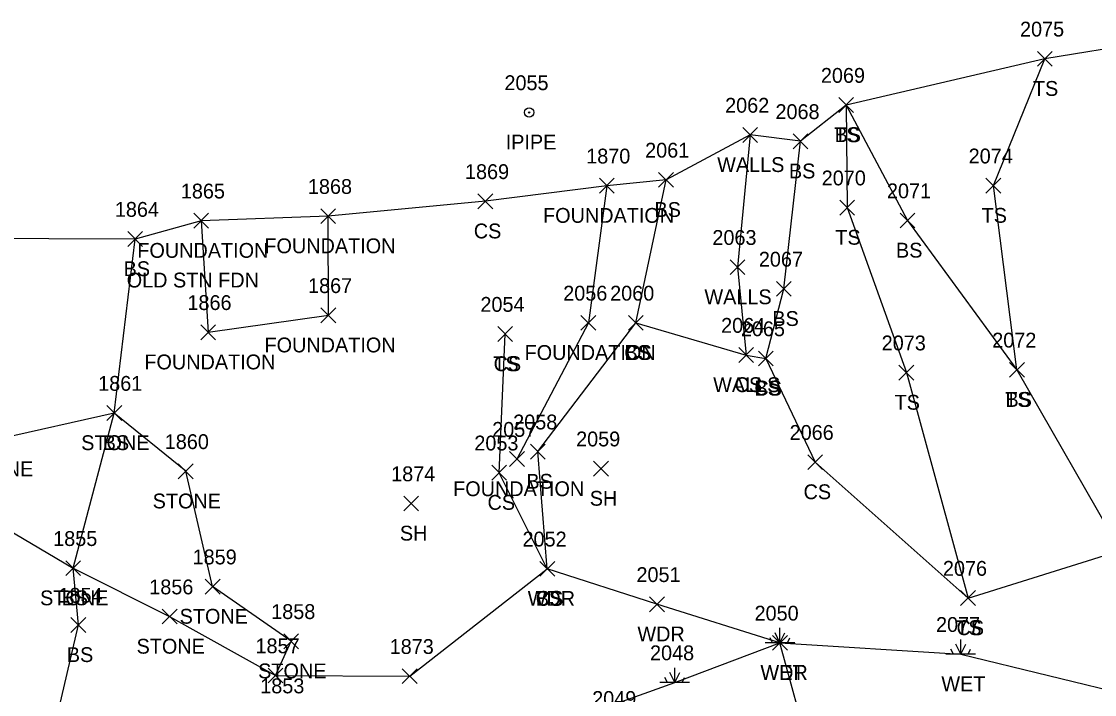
# Model space of a CAD drawing. Extents: x 1512665 to 1513714, y 110636 to 112816.
# Drawn here: x 1512769.8 to 1512914.5, y 110990.4 to 111081.2 of the extents above; entities that cross this region are included whole.
import ezdxf

# ---------------------------------------------------------------- set-up
doc = ezdxf.new("R2010")
doc.units = 0
for name, color, linetype in [('L_A', 7, 'Continuous'), ('L_C', 7, 'Continuous'), ('L_I', 7, 'Continuous'), ('L_TIC', 7, 'Continuous'), ('LASF', 7, 'Continuous'), ('LAWA', 7, 'Continuous'), ('LBC', 7, 'Continuous'), ('LELB', 7, 'Continuous'), ('LSOGP', 7, 'Continuous'), ('LWET', 7, 'Continuous'), ('LWS', 7, 'Continuous'), ('M_A', 7, 'Continuous'), ('M_I', 7, 'Continuous'), ('MPIP', 7, 'Continuous'), ('U_I', 7, 'Continuous')]:
    doc.layers.add(name, color=color, linetype=linetype)

msp = doc.modelspace()

# ---------------------------------------------------------------- linework, layer by layer
at = {"layer": 'L_TIC'}
for points in [[(1512906.8, 111075.13), (1512908.8, 111077.13)], [(1512908.8, 111075.13), (1512906.8, 111077.13)], [(1512880, 111068.89), (1512882, 111070.89)], [(1512882, 111068.89), (1512880, 111070.89)], [(1512880, 111068.89), (1512882, 111070.89)], [(1512882, 111068.89), (1512880, 111070.89)], [(1512867.07, 111064.86), (1512869.07, 111066.86)], [(1512869.07, 111064.86), (1512867.07, 111066.86)], [(1512873.85, 111064), (1512875.85, 111066)], [(1512875.85, 111064), (1512873.85, 111066)], [(1512847.72, 111058.01), (1512849.72, 111060.01)], [(1512849.72, 111058.01), (1512847.72, 111060.01)], [(1512855.71, 111058.8), (1512857.71, 111060.8)], [(1512857.71, 111058.8), (1512855.71, 111060.8)], [(1512899.87, 111058.02), (1512901.87, 111060.02)], [(1512901.87, 111058.02), (1512899.87, 111060.02)], [(1512831.34, 111055.91), (1512833.34, 111057.91)], [(1512833.34, 111055.91), (1512831.34, 111057.91)], [(1512880.14, 111055.06), (1512882.14, 111057.06)], [(1512882.14, 111055.06), (1512880.14, 111057.06)], [(1512793, 111053.29), (1512795, 111055.29)], [(1512795, 111053.29), (1512793, 111055.29)], [(1512810.14, 111053.91), (1512812.14, 111055.91)], [(1512812.14, 111053.91), (1512810.14, 111055.91)], [(1512888.28, 111053.32), (1512890.28, 111055.32)], [(1512890.28, 111053.32), (1512888.28, 111055.32)], [(1512784.1, 111050.82), (1512786.1, 111052.82)], [(1512786.1, 111050.82), (1512784.1, 111052.82)], [(1512865.35, 111047.03), (1512867.35, 111049.03)], [(1512867.35, 111047.03), (1512865.35, 111049.03)], [(1512871.61, 111044.1), (1512873.61, 111046.1)], [(1512873.61, 111044.1), (1512871.61, 111046.1)], [(1512810.16, 111040.54), (1512812.16, 111042.54)], [(1512812.16, 111040.54), (1512810.16, 111042.54)], [(1512845.23, 111039.52), (1512847.23, 111041.52)], [(1512847.23, 111039.52), (1512845.23, 111041.52)], [(1512851.64, 111039.52), (1512853.64, 111041.52)], [(1512853.64, 111039.52), (1512851.64, 111041.52)], [(1512851.64, 111039.52), (1512853.64, 111041.52)], [(1512853.64, 111039.52), (1512851.64, 111041.52)], [(1512793.94, 111038.25), (1512795.94, 111040.25)], [(1512795.94, 111038.25), (1512793.94, 111040.25)], [(1512834.01, 111038.01), (1512836.01, 111040.01)], [(1512836.01, 111038.01), (1512834.01, 111040.01)], [(1512834.01, 111038.01), (1512836.01, 111040.01)], [(1512836.01, 111038.01), (1512834.01, 111040.01)], [(1512866.53, 111035.18), (1512868.53, 111037.18)], [(1512868.53, 111035.18), (1512866.53, 111037.18)], [(1512866.53, 111035.18), (1512868.53, 111037.18)], [(1512868.53, 111035.18), (1512866.53, 111037.18)], [(1512869.18, 111034.72), (1512871.18, 111036.72)], [(1512871.18, 111034.72), (1512869.18, 111036.72)], [(1512869.18, 111034.72), (1512871.18, 111036.72)], [(1512871.18, 111034.72), (1512869.18, 111036.72)], [(1512903.05, 111033.19), (1512905.05, 111035.19)], [(1512905.05, 111033.19), (1512903.05, 111035.19)], [(1512903.05, 111033.19), (1512905.05, 111035.19)], [(1512905.05, 111033.19), (1512903.05, 111035.19)], [(1512888.13, 111032.81), (1512890.13, 111034.81)], [(1512890.13, 111032.81), (1512888.13, 111034.81)], [(1512781.28, 111027.36), (1512783.28, 111029.36)], [(1512783.28, 111027.36), (1512781.28, 111029.36)], [(1512781.28, 111027.36), (1512783.28, 111029.36)], [(1512783.28, 111027.36), (1512781.28, 111029.36)], [(1512838.42, 111022.15), (1512840.42, 111024.15)], [(1512840.42, 111022.15), (1512838.42, 111024.15)], [(1512835.6, 111021.15), (1512837.6, 111023.15)], [(1512837.6, 111021.15), (1512835.6, 111023.15)], [(1512846.93, 111019.86), (1512848.93, 111021.86)], [(1512848.93, 111019.86), (1512846.93, 111021.86)], [(1512875.82, 111020.74), (1512877.82, 111022.74)], [(1512877.82, 111020.74), (1512875.82, 111022.74)], [(1512790.92, 111019.5), (1512792.92, 111021.5)], [(1512792.92, 111019.5), (1512790.92, 111021.5)], [(1512833.19, 111019.31), (1512835.19, 111021.31)], [(1512835.19, 111019.31), (1512833.19, 111021.31)], [(1512821.32, 111015.16), (1512823.32, 111017.16)], [(1512823.32, 111015.16), (1512821.32, 111017.16)], [(1512775.73, 111006.43), (1512777.73, 111008.43)], [(1512777.73, 111006.43), (1512775.73, 111008.43)], [(1512775.73, 111006.43), (1512777.73, 111008.43)], [(1512777.73, 111006.43), (1512775.73, 111008.43)], [(1512839.69, 111006.36), (1512841.69, 111008.36)], [(1512841.69, 111006.36), (1512839.69, 111008.36)], [(1512839.69, 111006.36), (1512841.69, 111008.36)], [(1512841.69, 111006.36), (1512839.69, 111008.36)], [(1512839.69, 111006.36), (1512841.69, 111008.36)], [(1512841.69, 111006.36), (1512839.69, 111008.36)], [(1512794.55, 111003.95), (1512796.55, 111005.95)], [(1512796.55, 111003.95), (1512794.55, 111005.95)], [(1512854.49, 111001.57), (1512856.49, 111003.57)], [(1512856.49, 111001.57), (1512854.49, 111003.57)], [(1512896.45, 111002.41), (1512898.45, 111004.41)], [(1512898.45, 111002.41), (1512896.45, 111004.41)], [(1512896.45, 111002.41), (1512898.45, 111004.41)], [(1512898.45, 111002.41), (1512896.45, 111004.41)], [(1512788.75, 110999.91), (1512790.75, 111001.91)], [(1512790.75, 110999.91), (1512788.75, 111001.91)], [(1512776.44, 110998.78), (1512778.44, 111000.78)], [(1512778.44, 110998.78), (1512776.44, 111000.78)], [(1512805.14, 110996.58), (1512807.14, 110998.58)], [(1512807.14, 110996.58), (1512805.14, 110998.58)], [(1512871.08, 110996.37), (1512873.08, 110998.37)], [(1512873.08, 110996.37), (1512871.08, 110998.37)], [(1512803.03, 110991.96), (1512805.03, 110993.96)], [(1512805.03, 110991.96), (1512803.03, 110993.96)], [(1512803.03, 110991.96), (1512805.03, 110993.96)], [(1512805.03, 110991.96), (1512803.03, 110993.96)], [(1512821.13, 110991.87), (1512823.13, 110993.87)], [(1512823.13, 110991.87), (1512821.13, 110993.87)]]:
    msp.add_lwpolyline(points, dxfattribs=at)
at = {"layer": 'LASF'}
for points in [[(1512776.73, 111007.43), (1512789.75, 111000.91), (1512804.03, 110992.96), (1512806.14, 110997.58), (1512795.55, 111004.95), (1512791.92, 111020.5), (1512782.28, 111028.36), (1512766.6, 111024.83), (1512756.41, 111019.43)], [(1512756.41, 111019.43), (1512776.73, 111007.43)]]:
    msp.add_lwpolyline(points, dxfattribs=at)
at = {"layer": 'LAWA'}
msp.add_lwpolyline([(1512760.33, 110918.9), (1512772.72, 110925.35), (1512775.01, 110936.43), (1512792.55, 110938.68), (1512803.23, 110932.99), (1512815.95, 110931.19), (1512841.58, 110929.37), (1512844.09, 110932.41), (1512851.81, 110930.1), (1512861.96, 110937.34), (1512864.41, 110940.49), (1512867.9, 110945.24), (1512874.74, 110954.61), (1512875.76, 110966.44), (1512876.13, 110982.43), (1512872.08, 110997.37), (1512855.49, 111002.57), (1512840.69, 111007.36)], dxfattribs=at)
at = {"layer": 'LBC'}
for points in [[(1512848.72, 111059.01), (1512846.23, 111040.52), (1512836.6, 111022.15)], [(1512794, 111054.29), (1512794.94, 111039.25), (1512811.16, 111041.54), (1512811.14, 111054.91)]]:
    msp.add_lwpolyline(points, dxfattribs=at)
at = {"layer": 'LELB'}
for points in [[(1512904.05, 111034.19), (1512900.87, 111059.02), (1512907.8, 111076.13)], [(1512881, 111069.89), (1512881.14, 111056.06), (1512889.13, 111033.81), (1512897.45, 111003.41)], [(1512881, 111069.89), (1512889.28, 111054.32), (1512904.05, 111034.19), (1512918.02, 111009.83), (1512920.13, 110990.07), (1512909.26, 110972.23), (1512893.57, 110955.66)], [(1512870.18, 111035.72), (1512872.61, 111045.1), (1512874.85, 111065)], [(1512840.69, 111007.36), (1512839.42, 111023.15), (1512852.64, 111040.52), (1512856.71, 111059.8)], [(1512772.34, 110964.85), (1512772.4, 110978.17), (1512777.44, 110999.78), (1512776.73, 111007.43), (1512782.28, 111028.36), (1512785.1, 111051.82)], [(1512852.64, 111040.52), (1512867.53, 111036.18), (1512870.18, 111035.72), (1512876.82, 111021.74), (1512897.45, 111003.41), (1512918.02, 111009.83)], [(1512804.03, 110992.96), (1512822.13, 110992.87), (1512840.69, 111007.36), (1512834.19, 111020.31), (1512835.01, 111039.01)]]:
    msp.add_lwpolyline(points, dxfattribs=at)
at = {"layer": 'LSOGP'}
msp.add_lwpolyline([(1512921.08, 111078.29), (1512907.79, 111076.13), (1512881, 111069.89), (1512874.85, 111065), (1512868.07, 111065.86), (1512856.71, 111059.8), (1512848.73, 111059.01), (1512832.34, 111056.91), (1512811.14, 111054.91), (1512794, 111054.29), (1512785.1, 111051.82), (1512750.15, 111051.93)], dxfattribs=at)
at = {"layer": 'LWET'}
for p, q in [((1512872.08, 110997.37), (1512871.41, 110998.7)), ((1512872.08, 110997.37), (1512872.08, 110999.37)), ((1512872.08, 110997.37), (1512872.74, 110998.7)), ((1512874.08, 110997.37), (1512870.08, 110997.37)), ((1512871.08, 110997.37), (1512870.74, 110998.04)), ((1512873.08, 110997.37), (1512873.41, 110998.04)), ((1512896.47, 110995.84), (1512896.47, 110997.84)), ((1512898.47, 110995.84), (1512894.47, 110995.84)), ((1512895.47, 110995.84), (1512895.13, 110996.5)), ((1512896.47, 110995.84), (1512895.8, 110997.17)), ((1512896.47, 110995.84), (1512897.13, 110997.17)), ((1512897.47, 110995.84), (1512897.8, 110996.5)), ((1512857.89, 110992.02), (1512857.22, 110993.35)), ((1512857.89, 110992.02), (1512857.89, 110994.02)), ((1512857.89, 110992.02), (1512858.55, 110993.35)), ((1512859.89, 110992.02), (1512855.89, 110992.02)), ((1512856.89, 110992.02), (1512856.55, 110992.69)), ((1512858.89, 110992.02), (1512859.22, 110992.69))]:
    msp.add_line(p, q, dxfattribs=at)
msp.add_lwpolyline([(1512827.59, 110974.32), (1512838.97, 110985.23), (1512857.89, 110992.02), (1512872.08, 110997.37), (1512896.47, 110995.84), (1512920.13, 110990.07), (1512933.52, 110995.15), (1512956.57, 110999.31), (1512966.08, 111012.92), (1512978.76, 111015.54)], dxfattribs=at)
at = {"layer": 'LWS'}
msp.add_lwpolyline([(1512868.07, 111065.86), (1512866.35, 111048.03), (1512867.53, 111036.18)], dxfattribs=at)
at = {"layer": 'MPIP'}
for radius in [0.625, 0.0833]:
    msp.add_circle((1512838.25, 111068.9), radius, dxfattribs=at)

# ---------------------------------------------------------------- texts
at = {"layer": 'L_A'}
for s, p in [('TS', (1512906.2, 111071.13)), ('TS', (1512879.41, 111064.89)), ('BS', (1512879.44, 111064.89)), ('WALLS', (1512863.61, 111060.86)), ('BS', (1512873.29, 111060)), ('BS', (1512855.15, 111054.8)), ('FOUNDATION', (1512840.12, 111054.01)), ('TS', (1512899.28, 111054.02)), ('CS', (1512830.78, 111051.91)), ('TS', (1512879.55, 111051.06)), ('FOUNDATION', (1512785.39, 111049.29)), ('FOUNDATION', (1512802.53, 111049.91)), ('BS', (1512887.73, 111049.32)), ('BS', (1512783.54, 111046.82)), ('WALLS', (1512861.89, 111043.03)), ('BS', (1512871.05, 111040.1)), ('FOUNDATION', (1512802.55, 111036.54)), ('FOUNDATION', (1512837.63, 111035.52)), ('CS', (1512851.08, 111035.52)), ('BS', (1512851.08, 111035.52)), ('FOUNDATION', (1512786.34, 111034.25)), ('TS', (1512833.42, 111034.01)), ('CS', (1512833.45, 111034.01)), ('WALLS', (1512863.07, 111031.18)), ('CS', (1512865.97, 111031.18)), ('CS', (1512868.63, 111030.72)), ('BS', (1512868.63, 111030.72)), ('TS', (1512887.54, 111028.81)), ('TS', (1512902.46, 111029.19)), ('BS', (1512902.49, 111029.19)), ('STONE', (1512777.82, 111023.36)), ('BS', (1512780.72, 111023.36)), ('STONE', (1512762.15, 111019.83)), ('FOUNDATION', (1512827.99, 111017.15)), ('BS', (1512837.87, 111018.15)), ('STONE', (1512787.46, 111015.5)), ('SH', (1512846.42, 111015.86)), ('CS', (1512875.26, 111016.74)), ('CS', (1512832.63, 111015.31)), ('SH', (1512820.81, 111011.16)), ('STONE', (1512772.27, 111002.43)), ('BS', (1512775.17, 111002.43)), ('WDR', (1512838.05, 111002.36)), ('CS', (1512839.13, 111002.36)), ('BS', (1512839.13, 111002.36)), ('STONE', (1512791.1, 110999.95)), ('TS', (1512895.86, 110998.41)), ('CS', (1512895.89, 110998.41)), ('WDR', (1512852.85, 110997.57)), ('STONE', (1512785.29, 110995.91)), ('BS', (1512775.88, 110994.78)), ('STONE', (1512801.69, 110992.58)), ('WDR', (1512869.44, 110992.37)), ('WET', (1512869.45, 110992.37)), ('WET', (1512893.85, 110990.84))]:
    msp.add_text(s, height=2, dxfattribs=at).set_placement(p)
at = {"layer": 'L_C'}
msp.add_text('OLD STN FDN', height=2, dxfattribs=at).set_placement((1512783.96, 111045.29))
at = {"layer": 'L_I'}
for s, p in [('2075', (1512904.46, 111079.13)), ('2069', (1512877.6, 111072.89)), ('2069', (1512877.6, 111072.89)), ('2062', (1512864.68, 111068.86)), ('2068', (1512871.47, 111068)), ('1870', (1512845.94, 111062.01)), ('2061', (1512853.89, 111062.8)), ('2074', (1512897.53, 111062.02)), ('1869', (1512829.59, 111059.91)), ('2070', (1512877.71, 111059.06)), ('1868', (1512808.4, 111057.91)), ('1865', (1512791.26, 111057.29)), ('2071', (1512886.51, 111057.32)), ('1864', (1512782.36, 111054.82)), ('2063', (1512862.96, 111051.03)), ('2067', (1512869.23, 111048.1)), ('1867', (1512808.42, 111044.54)), ('2056', (1512842.84, 111043.52)), ('2060', (1512849.17, 111043.52)), ('2060', (1512849.17, 111043.52)), ('1866', (1512792.15, 111042.25)), ('2054', (1512831.67, 111042.01)), ('2054', (1512831.67, 111042.01)), ('2064', (1512864.14, 111039.18)), ('2064', (1512864.14, 111039.18)), ('2065', (1512866.8, 111038.72)), ('2065', (1512866.8, 111038.72)), ('2072', (1512900.71, 111037.19)), ('2072', (1512900.71, 111037.19)), ('2073', (1512885.8, 111036.81)), ('1861', (1512780.11, 111031.36)), ('1861', (1512780.11, 111031.36)), ('2058', (1512836.09, 111026.15)), ('2057', (1512833.26, 111025.15)), ('2066', (1512873.38, 111024.74)), ('1860', (1512789.09, 111023.5)), ('2053', (1512830.85, 111023.31)), ('2059', (1512844.58, 111023.86)), ('1874', (1512819.63, 111019.16)), ('1855', (1512774.04, 111010.43)), ('1855', (1512774.04, 111010.43)), ('2052', (1512837.35, 111010.36)), ('2052', (1512837.35, 111010.36)), ('2052', (1512837.35, 111010.36)), ('1859', (1512792.85, 111007.95)), ('2051', (1512852.72, 111005.57)), ('2076', (1512894.06, 111006.41)), ('2076', (1512894.06, 111006.41)), ('1856', (1512787, 111003.91)), ('1854', (1512774.75, 111002.78)), ('1858', (1512803.45, 111000.58)), ('2050', (1512868.65, 111000.37)), ('2050', (1512868.65, 111000.37)), ('2077', (1512893.13, 110998.84)), ('1857', (1512801.33, 110995.96)), ('1857', (1512801.33, 110995.96)), ('1873', (1512819.43, 110995.87)), ('2048', (1512854.55, 110995.02)), ('1853', (1512801.97, 110990.56))]:
    msp.add_text(s, height=2, dxfattribs=at).set_placement(p)
at = {"layer": 'M_A'}
msp.add_text('IPIPE', height=2, dxfattribs=at).set_placement((1512835.08, 111063.9))
at = {"layer": 'M_I'}
msp.add_text('2055', height=2, dxfattribs=at).set_placement((1512834.91, 111071.9))
at = {"layer": 'U_I'}
msp.add_text('2049', height=2, dxfattribs=at).set_placement((1512846.75, 110988.86))

doc.saveas('drawing.dxf')
